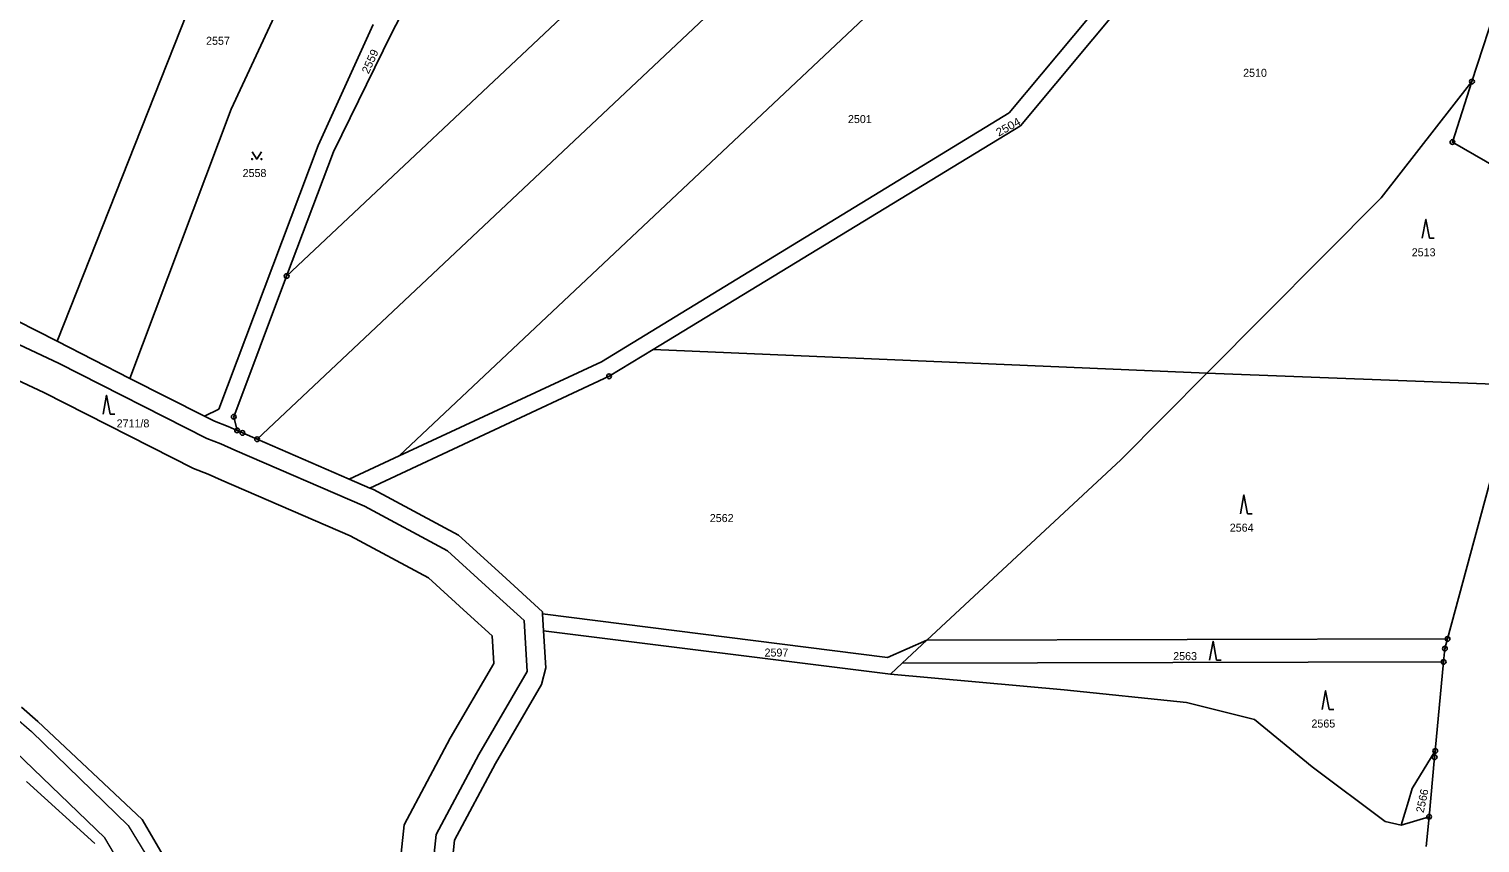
# Model space of a CAD drawing. Extents: x -606517 to -602431, y -1183120 to -1179397.
# Drawn here: x -605001.8 to -604693.5, y -1181219.7 to -1181046.7 of the extents above; entities that cross this region are included whole.
import ezdxf
from ezdxf.enums import TextEntityAlignment as Align

# ---------------------------------------------------------------- set-up
doc = ezdxf.new("R2010")
doc.units = 0
doc.header["$LTSCALE"] = 0.68
for name, color, linetype, lineweight in [('1', 7, 'Continuous', 25), ('3', 7, 'Continuous', 25), ('4', 7, 'Continuous', 13), ('8', 7, 'Continuous', 25)]:
    doc.layers.add(name, color=color, linetype=linetype, lineweight=lineweight)
doc.layers.add('2', color=7, linetype='Continuous')

msp = doc.modelspace()

# ---------------------------------------------------------------- linework, layer by layer
at = {"layer": '1'}
for p, q in [((-604947.06, -1181099.25), (-604840.66, -1180999.07)), ((-604953.33, -1181133.92), (-604815.93, -1181004.56)), ((-604785.78, -1181008.12), (-604923.13, -1181137.43)), ((-604995.84, -1181113.11), (-604956.44, -1181013.52)), ((-604751.9, -1181014.67), (-604793.54, -1181064.57)), ((-604791.14, -1181067.3), (-604747.23, -1181014.65)), ((-604683.36, -1181021.34), (-604695.19, -1181057.9)), ((-604942.89, -1181029.42), (-604958.82, -1181063.74)), ((-604921.05, -1181040.36), (-604924.8, -1181047.67)), ((-604940.36, -1181071.47), (-604928.68, -1181045.8)), ((-604924.8, -1181047.67), (-604937.13, -1181072.81)), ((-604714.47, -1181082.58), (-604695.19, -1181057.9)), ((-604695.19, -1181057.9), (-604699.35, -1181070.75)), ((-604958.82, -1181063.74), (-604980.35, -1181120.98)), ((-604793.54, -1181064.57), (-604880.19, -1181117.45)), ((-604869.21, -1181114.85), (-604791.14, -1181067.3)), ((-604961.45, -1181127.54), (-604940.36, -1181071.47)), ((-604699.35, -1181070.75), (-604687.65, -1181077.53)), ((-604937.13, -1181072.81), (-604947.06, -1181099.25)), ((-604751.54, -1181119.89), (-604714.47, -1181082.58)), ((-604995.57, -1181117.73), (-605064.44, -1181085.46)), ((-604995.84, -1181113.11), (-605027.68, -1181096.94)), ((-604958.3, -1181129.15), (-604947.06, -1181099.25)), ((-604980.35, -1181120.98), (-604995.84, -1181113.11)), ((-604964.02, -1181133.75), (-604995.57, -1181117.73)), ((-604880.19, -1181117.45), (-604923.13, -1181137.43)), ((-604878.56, -1181120.55), (-604869.21, -1181114.85)), ((-604869.21, -1181114.85), (-604751.54, -1181119.89)), ((-604929.36, -1181144.31), (-604878.56, -1181120.55)), ((-604751.54, -1181119.89), (-604769.81, -1181138.29)), ((-604686.89, -1181122.36), (-604751.54, -1181119.89)), ((-604980.35, -1181120.98), (-604964.49, -1181129.04)), ((-604964.49, -1181129.04), (-604961.45, -1181127.54)), ((-604964.49, -1181129.04), (-604962.41, -1181130.09)), ((-604962.41, -1181130.09), (-604959.48, -1181131.18)), ((-604957.6, -1181132.04), (-604958.3, -1181129.15)), ((-604959.48, -1181131.18), (-604957.6, -1181132.04)), ((-604956.45, -1181132.57), (-604957.6, -1181132.04)), ((-604953.33, -1181133.92), (-604956.45, -1181132.57)), ((-604688.26, -1181131.55), (-604700.39, -1181176.37)), ((-604961.02, -1181134.87), (-604964.02, -1181133.75)), ((-604958.08, -1181136.22), (-604961.02, -1181134.87)), ((-604930.49, -1181148.18), (-604958.08, -1181136.22)), ((-604933.79, -1181142.39), (-604953.33, -1181133.92)), ((-604923.13, -1181137.43), (-604933.79, -1181142.39)), ((-604769.81, -1181138.29), (-604811, -1181176.62)), ((-604933.79, -1181142.39), (-604929.36, -1181144.31)), ((-604928.62, -1181144.63), (-604929.36, -1181144.31)), ((-604910.52, -1181154.34), (-604928.62, -1181144.63)), ((-604912.85, -1181157.63), (-604930.49, -1181148.18)), ((-604901.3, -1181162.76), (-604910.52, -1181154.34)), ((-604904, -1181165.71), (-604912.85, -1181157.63)), ((-604892.72, -1181170.59), (-604901.3, -1181162.76)), ((-604896.61, -1181172.45), (-604904, -1181165.71)), ((-604895.95, -1181183.28), (-604896.61, -1181172.45)), ((-604892.69, -1181171.05), (-604892.72, -1181170.59)), ((-604892.69, -1181171.05), (-604892.47, -1181174.61)), ((-604819.38, -1181180.29), (-604892.69, -1181171.05)), ((-604891.99, -1181182.51), (-604892.47, -1181174.61)), ((-604892.47, -1181174.61), (-604818.75, -1181183.83)), ((-604811, -1181176.62), (-604819.38, -1181180.29)), ((-604816.26, -1181181.51), (-604811, -1181176.62)), ((-604811, -1181176.62), (-604700.39, -1181176.37)), ((-604700.94, -1181178.42), (-604701.21, -1181181.25)), ((-604700.39, -1181176.37), (-604700.94, -1181178.42)), ((-604892.93, -1181186.04), (-604891.99, -1181182.51)), ((-604818.75, -1181183.83), (-604816.26, -1181181.51)), ((-604701.21, -1181181.25), (-604816.26, -1181181.51)), ((-604702.99, -1181200.17), (-604701.21, -1181181.25)), ((-604906.21, -1181200.89), (-604895.95, -1181183.28)), ((-604818.75, -1181183.83), (-604781.85, -1181187.19)), ((-604902.71, -1181202.84), (-604892.93, -1181186.04)), ((-604781.85, -1181187.19), (-604755.86, -1181189.87)), ((-605003.38, -1181190.87), (-604999.9, -1181193.94)), ((-604755.86, -1181189.87), (-604741.37, -1181193.48)), ((-604999.9, -1181193.94), (-604977.78, -1181214.77)), ((-604741.37, -1181193.48), (-604729.16, -1181203.56)), ((-604915.29, -1181217.94), (-604906.21, -1181200.89)), ((-604702.99, -1181200.17), (-604707.89, -1181208.18)), ((-604703.12, -1181201.52), (-604702.99, -1181200.17)), ((-604911.39, -1181219.13), (-604902.71, -1181202.84)), ((-604729.16, -1181203.56), (-604713.63, -1181215.17)), ((-604704.31, -1181214.15), (-604703.12, -1181201.52)), ((-604987.82, -1181219.82), (-605002.33, -1181206.68)), ((-604707.89, -1181208.18), (-604708.68, -1181210.83)), ((-604708.68, -1181210.83), (-604710.22, -1181215.92)), ((-604977.78, -1181214.77), (-604966.06, -1181234.74)), ((-604713.63, -1181215.17), (-604710.22, -1181215.92)), ((-604710.22, -1181215.92), (-604704.31, -1181214.15)), ((-604704.31, -1181214.15), (-604704.91, -1181220.51)), ((-604917.2, -1181236.32), (-604915.29, -1181217.94)), ((-604913.12, -1181235.76), (-604911.39, -1181219.13))]:
    msp.add_line(p, q, dxfattribs=at)
msp.add_lwpolyline([(-604855.57, -1181294.85), (-604902.72, -1181270.57), (-604916.88, -1181256.29), (-604924.34, -1181237.29), (-604922.12, -1181215.85), (-604912.33, -1181197.46), (-604903.07, -1181181.59), (-604903.42, -1181175.71), (-604908.72, -1181170.89), (-604916.94, -1181163.39), (-604933.53, -1181154.48), (-604960.93, -1181142.61), (-604963.71, -1181141.34), (-604966.84, -1181140.17), (-604998.64, -1181124.02), (-605068.42, -1181091.31)], dxfattribs=at)
at = {"layer": '3'}
for p, q in [((-604704.24, -1181091.21), (-604703.244, -1181091.21)), ((-604984.58, -1181128.58), (-604983.584, -1181128.58)), ((-604742.91, -1181149.74), (-604741.914, -1181149.74)), ((-604749.45, -1181180.87), (-604748.454, -1181180.87)), ((-604725.55, -1181191.37), (-604724.554, -1181191.37))]:
    msp.add_line(p, q, dxfattribs=at)
for points in [[(-604954.42, -1181072.869), (-604953.42, -1181074.37), (-604952.42, -1181072.869)], [(-604704.24, -1181091.21), (-604704.99, -1181087.21), (-604705.74, -1181091.21)], [(-604984.58, -1181128.58), (-604985.33, -1181124.58), (-604986.08, -1181128.58)], [(-604742.91, -1181149.74), (-604743.66, -1181145.74), (-604744.41, -1181149.74)], [(-604749.45, -1181180.87), (-604750.2, -1181176.87), (-604750.95, -1181180.87)], [(-604725.55, -1181191.37), (-604726.3, -1181187.37), (-604727.05, -1181191.37)]]:
    msp.add_lwpolyline(points, dxfattribs=at)
for centre in [(-604954.42, -1181074.3695), (-604952.42, -1181074.3695)]:
    msp.add_circle(centre, 0.1, dxfattribs=at)
at = {"layer": '4'}
msp.add_line((-605005.01, -1181192.79), (-605001.28, -1181196.01), dxfattribs=at)
for points in [[(-605001.28, -1181196.01), (-604980.75, -1181216.03), (-604968.49, -1181236.12), (-604962.24, -1181255.66), (-604958.97, -1181274.58), (-604931.25, -1181447.71), (-604930.19, -1181474.9)], [(-604935.53, -1181475.1), (-604936.88, -1181448.29), (-604964.29, -1181275.49), (-604967.63, -1181256.05), (-604973.53, -1181239.25), (-604985.7, -1181218.67), (-605004.69, -1181200.39)]]:
    msp.add_lwpolyline(points, dxfattribs=at)
at = {"layer": '8'}
for centre, radius in [((-604695.19, -1181057.8999), 0.5), ((-604695.19, -1181057.8999), 0.0303), ((-604699.35, -1181070.7499), 0.5), ((-604699.35, -1181070.7499), 0.0303), ((-604947.06, -1181099.2499), 0.5), ((-604947.06, -1181099.2499), 0.0303), ((-604878.56, -1181120.5499), 0.5), ((-604878.56, -1181120.5499), 0.0303), ((-604958.3, -1181129.1499), 0.5), ((-604958.3, -1181129.1499), 0.0303), ((-604957.6, -1181132.0399), 0.5), ((-604957.6, -1181132.0399), 0.0303), ((-604956.45, -1181132.5699), 0.5), ((-604956.45, -1181132.5699), 0.0303), ((-604953.33, -1181133.9199), 0.5), ((-604953.33, -1181133.9199), 0.0303), ((-604700.39, -1181176.3699), 0.5), ((-604700.39, -1181176.3699), 0.0303), ((-604700.94, -1181178.4199), 0.5), ((-604700.94, -1181178.4199), 0.0303), ((-604701.21, -1181181.2499), 0.5), ((-604701.21, -1181181.2499), 0.0303), ((-604702.99, -1181200.1699), 0.5), ((-604702.99, -1181200.1699), 0.0303), ((-604703.12, -1181201.5199), 0.5), ((-604703.12, -1181201.5199), 0.0303), ((-604704.31, -1181214.1499), 0.5), ((-604704.31, -1181214.1499), 0.0303)]:
    msp.add_circle(centre, radius, dxfattribs=at)

# ---------------------------------------------------------------- texts
at = {"layer": '2'}
for s, p in [('2557', (-604964.18, -1181050.085)), ('2510', (-604743.82, -1181056.895)), ('2501', (-604827.79, -1181066.725)), ('2558', (-604956.42, -1181078.195)), ('2513', (-604707.99, -1181095.035)), ('2562', (-604857.15, -1181151.525)), ('2564', (-604746.66, -1181153.565)), ('2597', (-604845.51, -1181180.105)), ('2563', (-604758.68, -1181180.865)), ('2565', (-604729.3, -1181195.195))]:
    msp.add_text(s, height=1.7, dxfattribs=at).set_placement(p)
for s, rotation, width, p in [('2559', 66, 1.05, (-604929.641, -1181056.392)), ('2504', 29, 1.1, (-604795.763, -1181069.631))]:
    msp.add_text(s, height=1.7, rotation=rotation, dxfattribs=dict(at, width=width)).set_placement(p)
msp.add_text('2711/8', height=1.7, dxfattribs=at).set_placement((-604979.71, -1181131.405), align=Align.CENTER)
msp.add_text('2566', height=1.7, rotation=78, dxfattribs=at).set_placement((-604705.464, -1181213.418))

doc.saveas('drawing.dxf')
